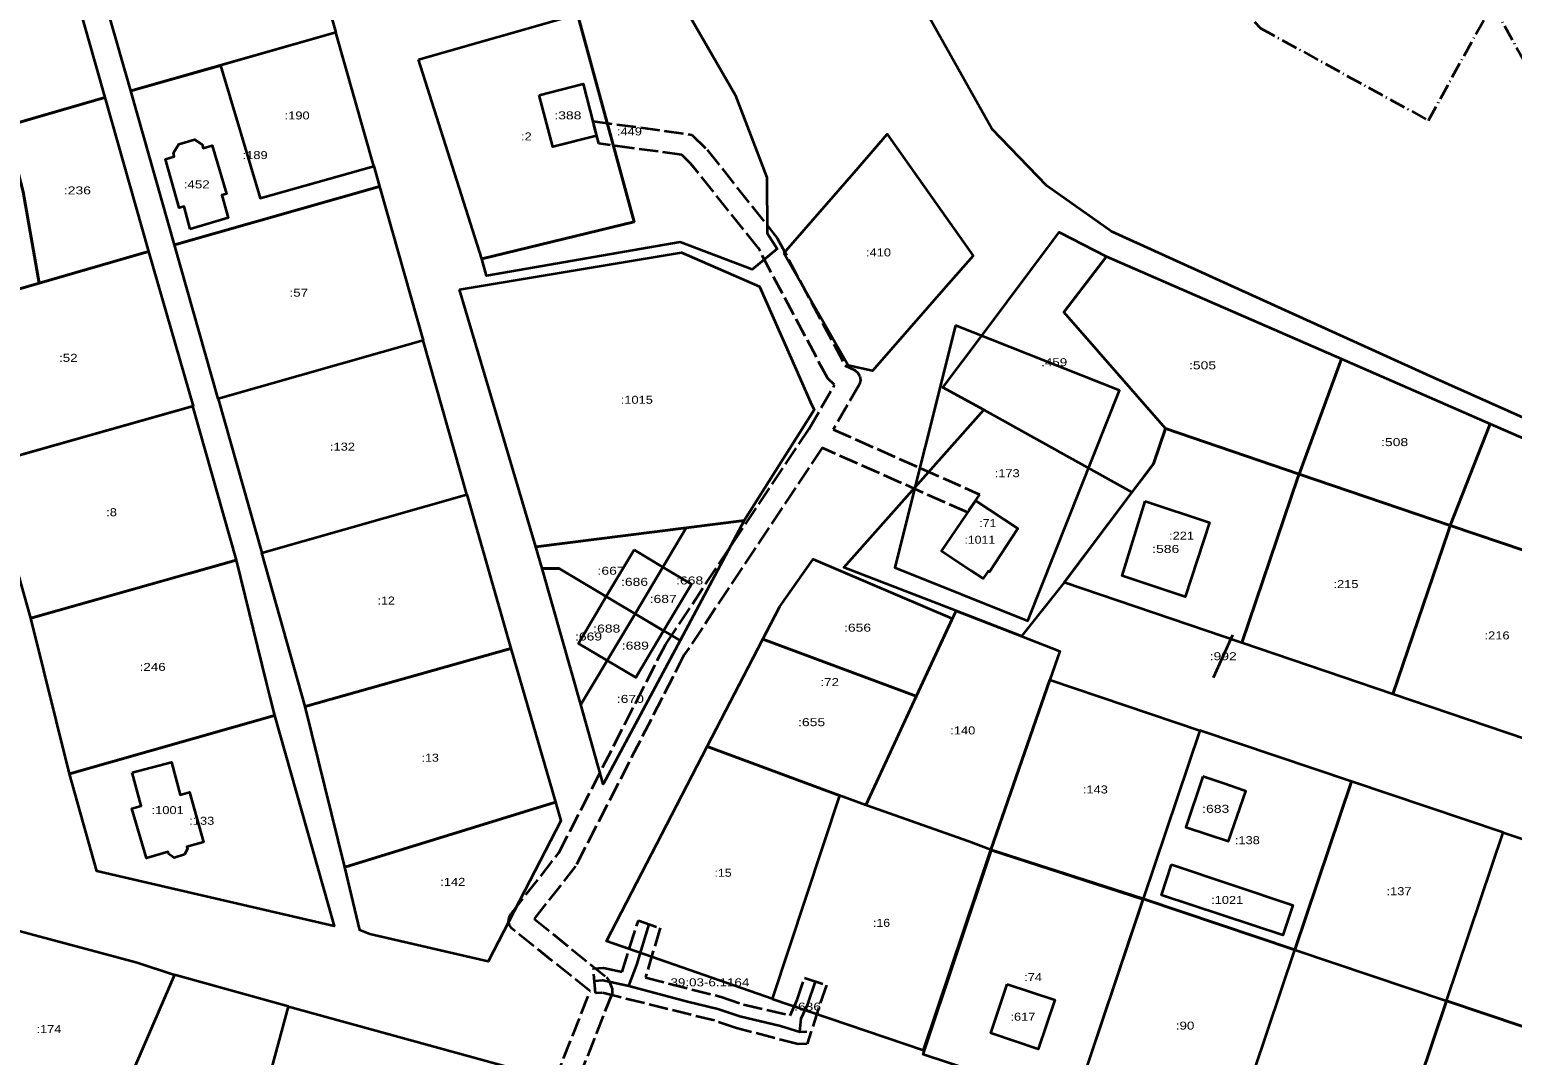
# Model space of a CAD drawing. Extents: x 1185507 to 1197690, y 352608 to 375774.
# Drawn here: x 1190399.7 to 1190677.6, y 364596.7 to 364788.9 of the extents above; entities that cross this region are included whole.
import ezdxf
from ezdxf.enums import TextEntityAlignment as Align

# ---------------------------------------------------------------- set-up
doc = ezdxf.new("R2010")
doc.units = 0
doc.header["$LTSCALE"] = 0.6
doc.linetypes.add('DOT_DASHED', pattern=[7.7, 5, -1.2, 0.3, -1.2])
doc.linetypes.add('LONG_DASHED', pattern=[7.5, 6, -1.5])
for name, color, linetype, lineweight in [('2', 7, 'Continuous', 35), ('4', 7, 'Continuous', 35), ('5', 7, 'DOT_DASHED', 35), ('7', 7, 'LONG_DASHED', 35), ('8', 7, 'Continuous', 35)]:
    doc.layers.add(name, color=color, linetype=linetype, lineweight=lineweight)

msp = doc.modelspace()

# ---------------------------------------------------------------- linework, layer by layer
at = {"layer": '2'}
for points in [[(1190375.34, 364765.08), (1190367.16, 364793.94), (1190405.58, 364805.04), (1190413.76, 364776.18)], [(1190452.97, 364802.88), (1190457.08, 364788.37), (1190418.6, 364777.46), (1190414.53, 364791.81)], [(1190502.39, 364791.82), (1190520.29, 364796.9), (1190531.93, 364776.72), (1190537.87, 364761.2), (1190537.94, 364750.76), (1190539.8, 364747.84), (1190535.12, 364743.94), (1190521.64, 364749.08), (1190485.31, 364742.8), (1190484.42, 364746), (1190513, 364752.9)], [(1190472.57, 364783.32), (1190502.39, 364791.82), (1190513, 364752.9), (1190484.42, 364746)], [(1190435.45, 364782.23), (1190442.88, 364757.31), (1190464.17, 364763.35), (1190457.08, 364788.37)], [(1190418.6, 364777.45), (1190435.45, 364782.23), (1190442.88, 364757.31), (1190464.17, 364763.35), (1190465.27, 364759.51), (1190426.79, 364748.6)], [(1190395.28, 364770.84), (1190413.76, 364776.18), (1190421.95, 364747.32), (1190401.46, 364741.41), (1190398.45, 364758.53), (1190396.46, 364766.26)], [(1190395.28, 364770.84), (1190396.46, 364766.26), (1190398.45, 364758.53), (1190401.46, 364741.41), (1190383.53, 364736.22), (1190375.34, 364765.08)], [(1190541.06, 364747.06), (1190555.03, 364763.1), (1190560.46, 364769.34), (1190576.55, 364746.52), (1190571.44, 364740.7), (1190557.67, 364725), (1190553.1, 364725.95)], [(1190426.79, 364748.6), (1190465.27, 364759.51), (1190473.46, 364730.65), (1190434.98, 364719.74)], [(1190578.51, 364731.96), (1190591.65, 364749.56), (1190592.7, 364750.97), (1190601.54, 364746.39), (1190597.66, 364741.34), (1190593.54, 364735.98), (1190612.59, 364714.15), (1190610.35, 364707.54), (1190609.22, 364706.04), (1190606.32, 364702.21), (1190578.56, 364717.68), (1190570.9, 364721.84)], [(1190383.53, 364736.22), (1190401.46, 364741.41), (1190421.95, 364747.32), (1190430.29, 364718.35), (1190391.8, 364707.51)], [(1190480.25, 364740.21), (1190521.89, 364747.13), (1190536.52, 364740.77), (1190543.39, 364725.23), (1190546.09, 364719.12), (1190546.74, 364717.64), (1190533.65, 364696.95), (1190494.59, 364691.98), (1190487.37, 364716.26)], [(1190593.54, 364735.98), (1190601.54, 364746.39), (1190645.59, 364727.22), (1190637.66, 364705.64), (1190612.59, 364714.15)], [(1190573.24, 364733.48), (1190561.89, 364688.14), (1190586.78, 364678.11), (1190603.99, 364721.29)], [(1190473.46, 364730.65), (1190434.98, 364719.74), (1190443.16, 364690.88), (1190481.64, 364701.79)], [(1190645.59, 364727.22), (1190673.49, 364715.07), (1190666, 364696.02), (1190637.66, 364705.64)], [(1190391.68, 364707.46), (1190430.17, 364718.37), (1190438.35, 364689.51), (1190399.87, 364678.6)], [(1190578.56, 364717.68), (1190606.32, 364702.21), (1190593.59, 364685.33), (1190585.65, 364675.22), (1190573.34, 364679.97), (1190552.28, 364688.12)], [(1190612.59, 364714.15), (1190637.66, 364705.64), (1190637.44, 364705), (1190626.91, 364674.01), (1190593.59, 364685.33), (1190610.35, 364707.54)], [(1190673.49, 364715.07), (1190700.36, 364703.38), (1190694.33, 364686.41), (1190666, 364696.02)], [(1190637.66, 364705.64), (1190666, 364696.02), (1190665.59, 364694.81), (1190655.25, 364664.39), (1190626.91, 364674.01), (1190637.44, 364705)], [(1190443.16, 364690.88), (1190481.64, 364701.79), (1190489.88, 364672.97), (1190451.3, 364662.07)], [(1190522.75, 364695.56), (1190533.65, 364696.95), (1190521.6, 364674.43), (1190513.16, 364679.46)], [(1190494.59, 364691.98), (1190522.75, 364695.56), (1190513.16, 364679.46), (1190498.91, 364687.93), (1190495.74, 364687.94)], [(1190666, 364696.02), (1190694.33, 364686.41), (1190693.73, 364684.63), (1190683.59, 364654.77), (1190655.25, 364664.39), (1190665.59, 364694.81)], [(1190399.87, 364678.6), (1190429, 364686.85), (1190430.01, 364687.14), (1190438.35, 364689.51), (1190444.03, 364666.59), (1190444.72, 364663.81), (1190445.58, 364660.37), (1190407.1, 364649.46)], [(1190495.74, 364687.94), (1190498.91, 364687.93), (1190513.16, 364679.46), (1190502.97, 364662.43)], [(1190526.66, 364654.55), (1190540.3, 364680.79), (1190546.56, 364689.69), (1190572.64, 364678.57), (1190556.42, 364643.59), (1190551.5, 364645.41)], [(1190537.12, 364674.67), (1190540.3, 364680.79), (1190546.56, 364689.69), (1190572.64, 364678.57), (1190565.88, 364664)], [(1190573.34, 364679.97), (1190585.65, 364675.22), (1190592.81, 364672.45), (1190590.93, 364667.04), (1190579.88, 364635.2), (1190575.72, 364636.79), (1190556.42, 364643.59)], [(1190513.16, 364679.46), (1190521.6, 364674.43), (1190507.2, 364647.53), (1190502.97, 364662.43)], [(1190526.66, 364654.55), (1190537.12, 364674.67), (1190565.88, 364664), (1190556.42, 364643.59), (1190551.5, 364645.41)], [(1190451.3, 364662.07), (1190489.88, 364672.97), (1190498.23, 364644.13), (1190458.75, 364631.97)], [(1190590.93, 364667.04), (1190619.05, 364657.59), (1190608.44, 364626), (1190579.88, 364635.2)], [(1190445.58, 364660.37), (1190456.76, 364620.93), (1190412.28, 364631.19), (1190407.1, 364649.46)], [(1190647.49, 364648.03), (1190619.05, 364657.59), (1190608.44, 364626), (1190636.88, 364616.44)], [(1190526.66, 364654.55), (1190551.5, 364645.41), (1190538.89, 364607.26), (1190507.84, 364618.08)], [(1190675.93, 364638.48), (1190647.49, 364648.03), (1190636.88, 364616.44), (1190665.31, 364606.88)], [(1190458.75, 364631.97), (1190498.23, 364644.13), (1190499.24, 364640.64), (1190485.63, 364614.28), (1190463.43, 364619.39), (1190461.54, 364620.13)], [(1190551.5, 364645.41), (1190538.89, 364607.26), (1190567.26, 364597.63), (1190579.88, 364635.2), (1190575.72, 364636.79), (1190556.42, 364643.59)], [(1190665.31, 364606.88), (1190675.93, 364638.48), (1190704.36, 364628.92), (1190693.75, 364597.33)], [(1190580.02, 364635.14), (1190608.39, 364625.95), (1190595.5, 364587.56), (1190567.19, 364596.87)], [(1190636.88, 364616.44), (1190608.44, 364626), (1190595.7, 364588.08), (1190624.14, 364578.52)], [(1190390.15, 364622), (1190419.82, 364614.11), (1190426.83, 364611.77), (1190415.6, 364585.92), (1190413.64, 364581.23), (1190379.72, 364591.89), (1190388.94, 364618.53)], [(1190636.88, 364616.44), (1190665.31, 364606.88), (1190652.56, 364568.96), (1190624.14, 364578.52)], [(1190448.18, 364605.82), (1190426.83, 364611.77), (1190415.6, 364585.92), (1190440.87, 364578.79)], [(1190448.18, 364605.82), (1190489.54, 364594.5), (1190482.19, 364567.48), (1190440.87, 364578.79)], [(1190665.31, 364606.88), (1190693.75, 364597.33), (1190681, 364559.41), (1190652.56, 364568.96)]]:
    msp.add_lwpolyline(points, close=True, dxfattribs=at)
at = {"layer": '4'}
msp.add_lwpolyline([(1191131.02, 364701.12), (1191053.29, 364581.4), (1191050.63, 364578.14), (1191040.71, 364565.72), (1191036.08, 364561.16), (1191028.92, 364560.8), (1191020.69, 364563.78), (1190972.52, 364589.14), (1190886.11, 364625.56), (1190799.83, 364662.85), (1190728.02, 364694.59), (1190662.22, 364723.99), (1190602.47, 364751.12), (1190590.37, 364759.65), (1190580.06, 364770.36), (1190547.33, 364828.67), (1190464.82, 364972.87), (1190441.49, 365013.05), (1190432.17, 365026.15), (1190413.53, 365042.81), (1190372.78, 365089.11)], dxfattribs=at)
at = {"layer": '5'}
msp.add_lwpolyline([(1190453.27, 365086.32), (1190473.13, 365060.86), (1190489.21, 365040.23), (1190507.68, 365016.55), (1190524.6, 364994.85), (1190540.63, 364974.3), (1190556.61, 364953.8), (1190572.6, 364933.3), (1190588.58, 364912.8), (1190604.57, 364892.29), (1190616.21, 364877.36), (1190588.5, 364837.85), (1190594.99, 364829.38), (1190603.93, 364817.92), (1190609.94, 364810.23), (1190630.45, 364789.19), (1190661.94, 364771.89), (1190673.89, 364793.66), (1190688.18, 364768.18)], dxfattribs=at)
at = {"layer": '7'}
for points in [[(1190390.14, 364566.2), (1190447.76, 364545.74), (1190451.22, 364554.84), (1190454.96, 364553.42), (1190451.55, 364544.45), (1190482.61, 364533.41), (1190494.81, 364583.53), (1190504.74, 364608.72), (1190490.08, 364620.47), (1190489.64, 364621.08), (1190489.45, 364621.8), (1190489.55, 364622.55), (1190489.92, 364623.22), (1190498.88, 364634.62), (1190518.92, 364673.75), (1190545.81, 364714.13), (1190550.54, 364722.34), (1190549.28, 364723.55), (1190536.3, 364747.95), (1190523.65, 364763.79), (1190521.95, 364765.46), (1190506.35, 364767.58), (1190505.27, 364771.78)], [(1190505.27, 364771.78), (1190523.82, 364769.24), (1190526.68, 364766.41), (1190539.84, 364749.83), (1190552.52, 364725.99), (1190554.38, 364725.08), (1190554.96, 364724.61), (1190555.32, 364723.95), (1190555.42, 364723.2), (1190555.23, 364722.48), (1190550.34, 364713.98), (1190577.75, 364701.82), (1190575.43, 364698.47), (1190548.23, 364710.55), (1190522.34, 364671.67), (1190502.02, 364632.14), (1190494.25, 364622.25), (1190507.83, 364611.34), (1190508.27, 364610.73), (1190508.88, 364609.16), (1190508.85, 364608.28), (1190498.64, 364582.41)]]:
    msp.add_lwpolyline(points, dxfattribs=at)
msp.add_lwpolyline([(1190505.37, 364612.94), (1190507.25, 364613.1), (1190510.72, 364612.34), (1190513.79, 364621.97), (1190517.88, 364620.57), (1190515.1, 364611.27), (1190529.31, 364607.65), (1190533.47, 364606.24), (1190542.24, 364604.17), (1190543.55, 364607.08), (1190544.93, 364611.24), (1190549.03, 364609.87), (1190547.57, 364605.5), (1190545.43, 364598.82), (1190543.72, 364598.78), (1190532.19, 364601.78), (1190528.03, 364603.19), (1190506.95, 364608.42), (1190505.76, 364608.32)], close=True, dxfattribs=at)
at = {"layer": '8'}
msp.add_line((1190621.64, 364667.5), (1190625.23, 364675.48), dxfattribs=at)
for points in [[(1190495.2, 364776.67), (1190503.45, 364778.78), (1190505.94, 364769), (1190497.74, 364766.94)], [(1190429.76, 364751.5), (1190428.6, 364755.76), (1190427.72, 364755.5), (1190425.1, 364764.64), (1190426.76, 364765.12), (1190426.6, 364765.82), (1190427.6, 364767.48), (1190430.55, 364768.35), (1190432, 364767.42), (1190432.2, 364766.73), (1190433.89, 364767.22), (1190436.57, 364758.17), (1190435.69, 364757.91), (1190436.86, 364753.63)], [(1190577.03, 364700.62), (1190584.96, 364695.44), (1190579.59, 364687.31), (1190579.37, 364687.45), (1190578.42, 364686.03), (1190576.15, 364687.56), (1190576.09, 364687.48), (1190570.64, 364691.15)], [(1190608.78, 364700.57), (1190620.84, 364696.57), (1190616.32, 364682.62), (1190604.48, 364686.58)], [(1190512.98, 364691.4), (1190518.37, 364688.2), (1190513.16, 364679.46), (1190507.78, 364682.66)], [(1190518.37, 364688.2), (1190523.73, 364685.01), (1190518.52, 364676.27), (1190513.16, 364679.46)], [(1190507.78, 364682.66), (1190513.16, 364679.46), (1190507.92, 364670.7), (1190502.56, 364673.89)], [(1190513.16, 364679.46), (1190518.52, 364676.27), (1190513.31, 364667.5), (1190507.92, 364670.7)], [(1190418.91, 364649.69), (1190426.25, 364651.64), (1190427.87, 364645.52), (1190429.6, 364646.01), (1190432.26, 364636.65), (1190429.16, 364635.79), (1190429.27, 364635.4), (1190428.71, 364634.3), (1190426.75, 364633.72), (1190425.71, 364634.47), (1190425.62, 364634.8), (1190421.54, 364633.66), (1190418.81, 364642.98), (1190420.56, 364643.45)], [(1190619.61, 364648.98), (1190616.41, 364639.45), (1190624.45, 364636.8), (1190627.67, 364646.23), (1190627.29, 364646.35), (1190623.57, 364647.64)], [(1190613.77, 364632.43), (1190636.51, 364624.84), (1190634.64, 364619.19), (1190611.86, 364626.72)], [(1190582.93, 364610), (1190591.88, 364607.09), (1190588.73, 364597.86), (1190579.9, 364600.84)]]:
    msp.add_lwpolyline(points, close=True, dxfattribs=at)
for points in [[(1190512.03, 364609.69), (1190513.53, 364613.66), (1190515.83, 364621.26)], [(1190505.57, 364610.63), (1190507.1, 364610.76), (1190512.03, 364609.69), (1190522.99, 364606.76), (1190528.67, 364605.42), (1190532.83, 364604.01), (1190540.44, 364602.19), (1190544.04, 364601.1), (1190545.38, 364601.13)], [(1190544.04, 364601.1), (1190544.34, 364603.58), (1190545.56, 364606.29), (1190546.98, 364610.55)]]:
    msp.add_lwpolyline(points, dxfattribs=at)

# ---------------------------------------------------------------- texts
at = {"layer": '2'}
for s, width, p in [(':190', 1.2, (1190449.81, 364772.09)), (':2', 1.2, (1190492.7855, 364768.16)), (':449', 1.2, (1190512.11, 364769.1)), (':189', 1.2, (1190441.935, 364764.665)), (':236', 1.3, (1190408.6155, 364758.045)), (':410', 1.2, (1190558.805, 364746.42)), (':57', 1.25, (1190450.1245, 364738.875)), (':52', 1.25, (1190406.9095, 364726.665)), (':459', 1.25, (1190591.7455, 364725.84)), (':505', 1.3, (1190619.5655, 364725.265)), (':1015', 1.2, (1190513.4955, 364718.805)), (':132', 1.2, (1190458.31, 364710.015)), (':508', 1.3, (1190655.5755, 364710.87)), (':173', 1.2, (1190582.94, 364705.045)), (':8', 1.2, (1190415.0155, 364697.735)), (':71', 1.15, (1190579.3, 364695.7)), (':221', 1.2, (1190615.625, 364693.33)), (':667', 1.3, (1190508.6705, 364686.76)), (':668', 1.3, (1190523.4055, 364684.94)), (':215', 1.2, (1190646.455, 364684.265)), (':12', 1.15, (1190466.52, 364681.18)), (':656', 1.3, (1190554.8805, 364676.095)), (':669', 1.3, (1190504.4505, 364674.435)), (':216', 1.2, (1190674.79, 364674.645)), (':246', 1.25, (1190422.7255, 364668.735)), (':72', 1.25, (1190549.6495, 364665.89)), (':670', 1.3, (1190512.2855, 364662.745)), (':655', 1.3, (1190546.2705, 364658.38)), (':140', 1.2, (1190574.615, 364656.835)), (':13', 1.15, (1190474.765, 364651.72)), (':143', 1.2, (1190599.465, 364645.77)), (':133', 1.2, (1190431.93, 364639.9)), (':138', 1.2, (1190627.965, 364636.265)), (':142', 1.2, (1190478.995, 364628.455)), (':15', 1.15, (1190529.67, 364630.155)), (':137', 1.2, (1190656.405, 364626.705)), (':16', 1.15, (1190559.385, 364620.77)), (':74', 1.2, (1190587.7895, 364610.6)), (':174', 1.2, (1190403.275, 364600.865)), (':90', 1.25, (1190616.2895, 364601.51))]:
    msp.add_text(s, height=1.5, dxfattribs=dict(at, width=width)).set_placement(p, align=Align.CENTER)
at = {"layer": '7', "width": 1.25}
msp.add_text('39:03-6.1164', height=1.5, dxfattribs=at).set_placement((1190527.1995, 364609.625), align=Align.CENTER)
at = {"layer": '8'}
for s, width, p in [(':388', 1.3, (1190500.5705, 364772.11)), (':452', 1.25, (1190430.9805, 364759.175)), (':1011', 1.15, (1190577.8, 364692.575)), (':586', 1.3, (1190612.6605, 364690.845)), (':686', 1.3, (1190513.0755, 364684.68)), (':687', 1.3, (1190518.4455, 364681.485)), (':688', 1.3, (1190507.8605, 364675.93)), (':689', 1.3, (1190513.2205, 364672.73)), (':992', 1.3, (1190623.4355, 364670.74)), (':1001', 1.2, (1190425.5355, 364641.9)), (':683', 1.3, (1190622.0405, 364642.14)), (':1021', 1.2, (1190624.1855, 364625.06)), (':636', 1.3, (1190545.5105, 364605.075)), (':617', 1.2, (1190585.89, 364603.18))]:
    msp.add_text(s, height=1.5, dxfattribs=dict(at, width=width)).set_placement(p, align=Align.CENTER)

doc.saveas('drawing.dxf')
